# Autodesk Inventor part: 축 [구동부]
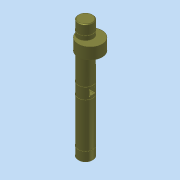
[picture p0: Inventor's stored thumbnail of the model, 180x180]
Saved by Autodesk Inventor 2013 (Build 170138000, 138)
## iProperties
Company: 한국ATC센터
Created: 2015-04
Part Number: 축 [구동부]
Document SubType Name: Modeling
Designer: KYOUNG IL JANG
Density: 1 g/cm^3
Material: 강철
Mass: 77.3127 g
Surface Area: 163.755 cm^2
Volume: 77.3127 cm^3
Author: KYOUNG IL JANG
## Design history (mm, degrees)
sketch "스케치1"
  geometry: C1 r 11 at (0, 0); 1 further point
  constraints: 1 centre point, 1 coincident
  dimensions: "d0" = 22 diameter of C1
extrude "돌출1" new body sketch "스케치1" stored distance "d1" = 180; taper "d2" = 0 deg
sketch "스케치2"
  geometry: L1 (-10.247, -4)-(10.247, -4); L2 (-10.247, 4)-(10.247, 4); A1 r 11 centre (0, 0) between (-10.247, -4) and (10.247, -4) reference; 1 further point
  constraints: 4 end point, 4 point on circle, 2 parallel, 1 horizontal
  dimensions: "d3" = 8 distance between parallel lines of L2 L1
extrude "돌출2" cut sketch "스케치2" stored distance "d4" = 8; taper "d5" = 0 deg
sketch "스케치3"
  geometry: 5 further points
hole "구멍1" sketch "스케치3" at (-4, 4), (4, 4), (4, -4), (-4, -4) diameter "d6" = 2; stored, may be unused: countersink angle "d10" = 90 deg, drill point angle "d12" = 118 deg; dims "d7" = 6, "d8" = 4, "d9" = 2, "d11" = 8
chamfer "모따기1" distance "d13" = 1; stored, may be unused: second distance "d14" = 2, angle "d15" = 45 deg
sketch "스케치4"
  geometry: L1 (-10, 9)-(-11, 9); L2 (-11, 9)-(-11, 7.8); L3 (-11, 7.8)-(-10, 7.8); L4 (-10, 7.8)-(-10, 9); L5 (-10, 90)-(10, 90) reference; L6 (0, -15)-(0, 90) reference; L7 (-10, 74.8)-(-11, 74.8); L8 (-11, 74.8)-(-11, 76); L9 (-11, 76)-(-10, 76); L10 (-10, 76)-(-10, 74.8); 1 further point
  constraints: 16 end point, 4 parallel, 2 equal length, 2 horizontal, 2 perpendicular, 1 collinear
  dimensions: "d16" = 7.8 distance from line of L3 point (0, 0); "d17" = 82.2 distance between parallel lines of L3 L5 (derived); "d18" = 11 distance from line of point (0, 0) L2; "d19" = 1 distance of L2.end L3.end; "d20" = 1.2 distance of L1.end L2.end; "d27" = 14 distance between parallel lines of L5 L9
revolve "회전1" sketch "스케치4" stored, may be unused: angle "d21" = 90 deg
sketch "스케치5"
  geometry: L1 (11, 52)-(-7, 52); L2 (-7, 52)-(-7, 69); L3 (-7, 69)-(11, 69); L4 (11, 69)-(11, 52); 1 further point
  constraints: 8 end point, 2 parallel, 1 horizontal, 1 perpendicular
  dimensions: "d22" = 17 distance of L3.end L1.start; "d23" = 36 diameter of L4 L2; "d24" = 7 horizontal distance of L2.end point (0, 0); "d25" = 52 distance from line of L1 point (0, 0)
revolve "회전2" sketch "스케치5" stored, may be unused: angle "d26" = 90 deg
node "솔리드1"
mirror "대칭1"
mirror "대칭2"
